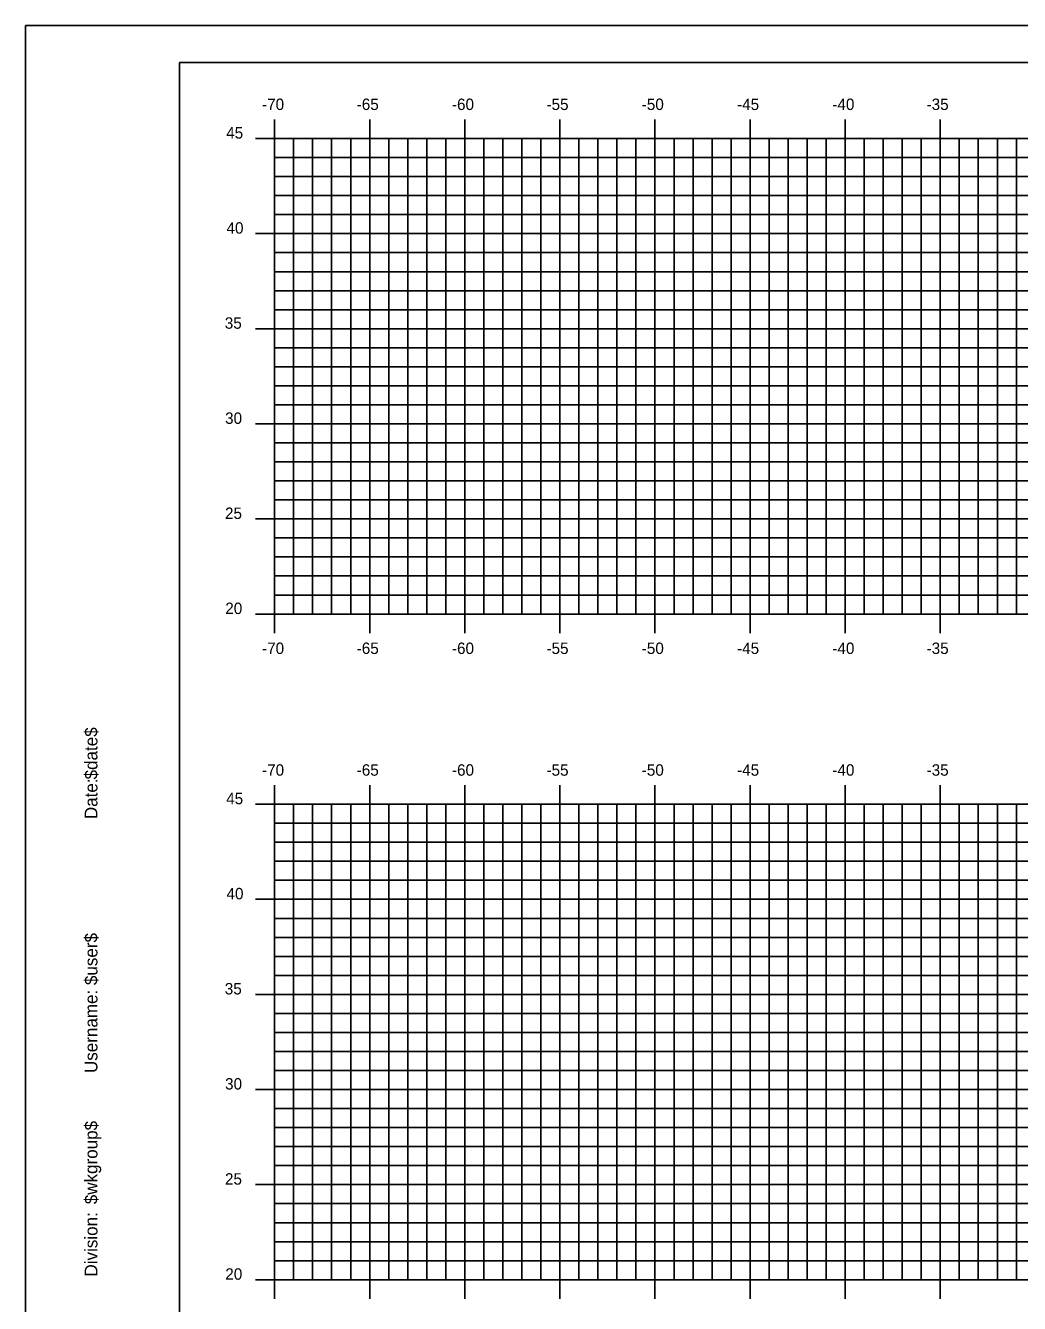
# Model space of a CAD drawing. Extents: x 1025909 to 1026079, y 394697 to 394807.
# Drawn here: x 1025908.6 to 1025960.8, y 394739.4 to 394806.5 of the extents above; entities that cross this region are included whole.
import ezdxf

# ---------------------------------------------------------------- set-up
doc = ezdxf.new("R2010")
doc.units = 0
for name, color, linetype in [('BORDER', 7, 'Continuous'), ('H_V ANNOTATION', 7, 'Continuous'), ('MAJOR', 7, 'Continuous'), ('MINOR', 7, 'Continuous'), ('PLOT BOUNDARY', 7, 'Continuous')]:
    doc.layers.add(name, color=color, linetype=linetype)

msp = doc.modelspace()

# ---------------------------------------------------------------- linework, layer by layer
at = {"layer": 'BORDER'}
for p, q in [((1026076.677, 394804.607), (1025916.677, 394804.607)), ((1025916.677, 394804.607), (1025916.677, 394699.607))]:
    msp.add_line(p, q, dxfattribs=at)
at = {"layer": 'MAJOR'}
for p, q in [((1025921.677, 394801.609), (1025921.677, 394800.607)), ((1025926.677, 394801.609), (1025926.677, 394800.607)), ((1025931.677, 394801.609), (1025931.677, 394800.607)), ((1025936.677, 394801.609), (1025936.677, 394800.607)), ((1025941.677, 394801.609), (1025941.677, 394800.607)), ((1025946.677, 394801.609), (1025946.677, 394800.607)), ((1025951.677, 394801.609), (1025951.677, 394800.607)), ((1025956.677, 394801.609), (1025956.677, 394800.607)), ((1025920.675, 394800.607), (1025921.677, 394800.607)), ((1025921.677, 394800.607), (1026061.677, 394800.607)), ((1025921.677, 394775.607), (1025921.677, 394800.607)), ((1025926.677, 394775.607), (1025926.677, 394800.607)), ((1025931.677, 394775.607), (1025931.677, 394800.607)), ((1025936.677, 394775.607), (1025936.677, 394800.607)), ((1025941.677, 394775.607), (1025941.677, 394800.607)), ((1025946.677, 394775.607), (1025946.677, 394800.607)), ((1025951.677, 394775.607), (1025951.677, 394800.607)), ((1025956.677, 394775.607), (1025956.677, 394800.607)), ((1025920.675, 394795.607), (1025921.677, 394795.607)), ((1025921.677, 394795.607), (1026061.677, 394795.607)), ((1025920.675, 394790.607), (1025921.677, 394790.607)), ((1025921.677, 394790.607), (1026061.677, 394790.607)), ((1025920.675, 394785.607), (1025921.677, 394785.607)), ((1025921.677, 394785.607), (1026061.677, 394785.607)), ((1025920.675, 394780.607), (1025921.677, 394780.607)), ((1025921.677, 394780.607), (1026061.677, 394780.607)), ((1025920.675, 394775.607), (1025921.677, 394775.607)), ((1025921.677, 394775.607), (1026061.677, 394775.607)), ((1025921.677, 394774.605), (1025921.677, 394775.607)), ((1025926.677, 394774.605), (1025926.677, 394775.607)), ((1025931.677, 394774.605), (1025931.677, 394775.607)), ((1025936.677, 394774.605), (1025936.677, 394775.607)), ((1025941.677, 394774.605), (1025941.677, 394775.607)), ((1025946.677, 394774.605), (1025946.677, 394775.607)), ((1025951.677, 394774.605), (1025951.677, 394775.607)), ((1025956.677, 394774.605), (1025956.677, 394775.607)), ((1025921.677, 394766.609), (1025921.677, 394765.607)), ((1025926.677, 394766.609), (1025926.677, 394765.607)), ((1025931.677, 394766.609), (1025931.677, 394765.607)), ((1025936.677, 394766.609), (1025936.677, 394765.607)), ((1025941.677, 394766.609), (1025941.677, 394765.607)), ((1025946.677, 394766.609), (1025946.677, 394765.607)), ((1025951.677, 394766.609), (1025951.677, 394765.607)), ((1025956.677, 394766.609), (1025956.677, 394765.607)), ((1025920.675, 394765.607), (1025921.677, 394765.607)), ((1025921.677, 394765.607), (1026061.677, 394765.607)), ((1025921.677, 394740.607), (1025921.677, 394765.607)), ((1025926.677, 394740.607), (1025926.677, 394765.607)), ((1025931.677, 394740.607), (1025931.677, 394765.607)), ((1025936.677, 394740.607), (1025936.677, 394765.607)), ((1025941.677, 394740.607), (1025941.677, 394765.607)), ((1025946.677, 394740.607), (1025946.677, 394765.607)), ((1025951.677, 394740.607), (1025951.677, 394765.607)), ((1025956.677, 394740.607), (1025956.677, 394765.607)), ((1025920.675, 394760.607), (1025921.677, 394760.607)), ((1025921.677, 394760.607), (1026061.677, 394760.607)), ((1025920.675, 394755.607), (1025921.677, 394755.607)), ((1025921.677, 394755.607), (1026061.677, 394755.607)), ((1025920.675, 394750.607), (1025921.677, 394750.607)), ((1025921.677, 394750.607), (1026061.677, 394750.607)), ((1025920.675, 394745.607), (1025921.677, 394745.607)), ((1025921.677, 394745.607), (1026061.677, 394745.607)), ((1025920.675, 394740.607), (1025921.677, 394740.607)), ((1025921.677, 394740.607), (1026061.677, 394740.607)), ((1025921.677, 394739.605), (1025921.677, 394740.607)), ((1025926.677, 394739.605), (1025926.677, 394740.607)), ((1025931.677, 394739.605), (1025931.677, 394740.607)), ((1025936.677, 394739.605), (1025936.677, 394740.607)), ((1025941.677, 394739.605), (1025941.677, 394740.607)), ((1025946.677, 394739.605), (1025946.677, 394740.607)), ((1025951.677, 394739.605), (1025951.677, 394740.607)), ((1025956.677, 394739.605), (1025956.677, 394740.607))]:
    msp.add_line(p, q, dxfattribs=at)
at = {"layer": 'MINOR'}
for p, q in [((1025922.677, 394775.607), (1025922.677, 394800.607)), ((1025923.677, 394775.607), (1025923.677, 394800.607)), ((1025924.677, 394775.607), (1025924.677, 394800.607)), ((1025925.677, 394775.607), (1025925.677, 394800.607)), ((1025927.677, 394775.607), (1025927.677, 394800.607)), ((1025928.677, 394775.607), (1025928.677, 394800.607)), ((1025929.677, 394775.607), (1025929.677, 394800.607)), ((1025930.677, 394775.607), (1025930.677, 394800.607)), ((1025932.677, 394775.607), (1025932.677, 394800.607)), ((1025933.677, 394775.607), (1025933.677, 394800.607)), ((1025934.677, 394775.607), (1025934.677, 394800.607)), ((1025935.677, 394775.607), (1025935.677, 394800.607)), ((1025937.677, 394775.607), (1025937.677, 394800.607)), ((1025938.677, 394775.607), (1025938.677, 394800.607)), ((1025939.677, 394775.607), (1025939.677, 394800.607)), ((1025940.677, 394775.607), (1025940.677, 394800.607)), ((1025942.677, 394775.607), (1025942.677, 394800.607)), ((1025943.677, 394775.607), (1025943.677, 394800.607)), ((1025944.677, 394775.607), (1025944.677, 394800.607)), ((1025945.677, 394775.607), (1025945.677, 394800.607)), ((1025947.677, 394775.607), (1025947.677, 394800.607)), ((1025948.677, 394775.607), (1025948.677, 394800.607)), ((1025949.677, 394775.607), (1025949.677, 394800.607)), ((1025950.677, 394775.607), (1025950.677, 394800.607)), ((1025952.677, 394775.607), (1025952.677, 394800.607)), ((1025953.677, 394775.607), (1025953.677, 394800.607)), ((1025954.677, 394775.607), (1025954.677, 394800.607)), ((1025955.677, 394775.607), (1025955.677, 394800.607)), ((1025957.677, 394775.607), (1025957.677, 394800.607)), ((1025958.677, 394775.607), (1025958.677, 394800.607)), ((1025959.677, 394775.607), (1025959.677, 394800.607)), ((1025960.677, 394775.607), (1025960.677, 394800.607)), ((1025921.677, 394799.607), (1026061.677, 394799.607)), ((1025921.677, 394799.607), (1025922.679, 394799.607)), ((1025921.677, 394798.607), (1026061.677, 394798.607)), ((1025921.677, 394798.607), (1025922.679, 394798.607)), ((1025921.677, 394797.607), (1026061.677, 394797.607)), ((1025921.677, 394797.607), (1025922.679, 394797.607)), ((1025921.677, 394796.607), (1026061.677, 394796.607)), ((1025921.677, 394796.607), (1025922.679, 394796.607)), ((1025921.677, 394794.607), (1026061.677, 394794.607)), ((1025921.677, 394794.607), (1025922.679, 394794.607)), ((1025921.677, 394793.607), (1026061.677, 394793.607)), ((1025921.677, 394793.607), (1025922.679, 394793.607)), ((1025921.677, 394792.607), (1026061.677, 394792.607)), ((1025921.677, 394792.607), (1025922.679, 394792.607)), ((1025921.677, 394791.607), (1026061.677, 394791.607)), ((1025921.677, 394791.607), (1025922.679, 394791.607)), ((1025921.677, 394789.607), (1026061.677, 394789.607)), ((1025921.677, 394789.607), (1025922.679, 394789.607)), ((1025921.677, 394788.607), (1026061.677, 394788.607)), ((1025921.677, 394788.607), (1025922.679, 394788.607)), ((1025921.677, 394787.607), (1026061.677, 394787.607)), ((1025921.677, 394787.607), (1025922.679, 394787.607)), ((1025921.677, 394786.607), (1026061.677, 394786.607)), ((1025921.677, 394786.607), (1025922.679, 394786.607)), ((1025921.677, 394784.607), (1026061.677, 394784.607)), ((1025921.677, 394784.607), (1025922.679, 394784.607)), ((1025921.677, 394783.607), (1026061.677, 394783.607)), ((1025921.677, 394783.607), (1025922.679, 394783.607)), ((1025921.677, 394782.607), (1026061.677, 394782.607)), ((1025921.677, 394782.607), (1025922.679, 394782.607)), ((1025921.677, 394781.607), (1026061.677, 394781.607)), ((1025921.677, 394781.607), (1025922.679, 394781.607)), ((1025921.677, 394779.607), (1026061.677, 394779.607)), ((1025921.677, 394779.607), (1025922.679, 394779.607)), ((1025921.677, 394778.607), (1026061.677, 394778.607)), ((1025921.677, 394778.607), (1025922.679, 394778.607)), ((1025921.677, 394777.607), (1026061.677, 394777.607)), ((1025921.677, 394777.607), (1025922.679, 394777.607)), ((1025921.677, 394776.607), (1026061.677, 394776.607)), ((1025921.677, 394776.607), (1025922.679, 394776.607)), ((1025922.677, 394740.607), (1025922.677, 394765.607)), ((1025923.677, 394740.607), (1025923.677, 394765.607)), ((1025924.677, 394740.607), (1025924.677, 394765.607)), ((1025925.677, 394740.607), (1025925.677, 394765.607)), ((1025927.677, 394740.607), (1025927.677, 394765.607)), ((1025928.677, 394740.607), (1025928.677, 394765.607)), ((1025929.677, 394740.607), (1025929.677, 394765.607)), ((1025930.677, 394740.607), (1025930.677, 394765.607)), ((1025932.677, 394740.607), (1025932.677, 394765.607)), ((1025933.677, 394740.607), (1025933.677, 394765.607)), ((1025934.677, 394740.607), (1025934.677, 394765.607)), ((1025935.677, 394740.607), (1025935.677, 394765.607)), ((1025937.677, 394740.607), (1025937.677, 394765.607)), ((1025938.677, 394740.607), (1025938.677, 394765.607)), ((1025939.677, 394740.607), (1025939.677, 394765.607)), ((1025940.677, 394740.607), (1025940.677, 394765.607)), ((1025942.677, 394740.607), (1025942.677, 394765.607)), ((1025943.677, 394740.607), (1025943.677, 394765.607)), ((1025944.677, 394740.607), (1025944.677, 394765.607)), ((1025945.677, 394740.607), (1025945.677, 394765.607)), ((1025947.677, 394740.607), (1025947.677, 394765.607)), ((1025948.677, 394740.607), (1025948.677, 394765.607)), ((1025949.677, 394740.607), (1025949.677, 394765.607)), ((1025950.677, 394740.607), (1025950.677, 394765.607)), ((1025952.677, 394740.607), (1025952.677, 394765.607)), ((1025953.677, 394740.607), (1025953.677, 394765.607)), ((1025954.677, 394740.607), (1025954.677, 394765.607)), ((1025955.677, 394740.607), (1025955.677, 394765.607)), ((1025957.677, 394740.607), (1025957.677, 394765.607)), ((1025958.677, 394740.607), (1025958.677, 394765.607)), ((1025959.677, 394740.607), (1025959.677, 394765.607)), ((1025960.677, 394740.607), (1025960.677, 394765.607)), ((1025921.677, 394764.607), (1026061.677, 394764.607)), ((1025921.677, 394764.607), (1025922.679, 394764.607)), ((1025921.677, 394763.607), (1026061.677, 394763.607)), ((1025921.677, 394763.607), (1025922.679, 394763.607)), ((1025921.677, 394762.607), (1026061.677, 394762.607)), ((1025921.677, 394762.607), (1025922.679, 394762.607)), ((1025921.677, 394761.607), (1026061.677, 394761.607)), ((1025921.677, 394761.607), (1025922.679, 394761.607)), ((1025921.677, 394759.607), (1026061.677, 394759.607)), ((1025921.677, 394759.607), (1025922.679, 394759.607)), ((1025921.677, 394758.607), (1026061.677, 394758.607)), ((1025921.677, 394758.607), (1025922.679, 394758.607)), ((1025921.677, 394757.607), (1026061.677, 394757.607)), ((1025921.677, 394757.607), (1025922.679, 394757.607)), ((1025921.677, 394756.607), (1026061.677, 394756.607)), ((1025921.677, 394756.607), (1025922.679, 394756.607)), ((1025921.677, 394754.607), (1026061.677, 394754.607)), ((1025921.677, 394754.607), (1025922.679, 394754.607)), ((1025921.677, 394753.607), (1026061.677, 394753.607)), ((1025921.677, 394753.607), (1025922.679, 394753.607)), ((1025921.677, 394752.607), (1026061.677, 394752.607)), ((1025921.677, 394752.607), (1025922.679, 394752.607)), ((1025921.677, 394751.607), (1026061.677, 394751.607)), ((1025921.677, 394751.607), (1025922.679, 394751.607)), ((1025921.677, 394749.607), (1026061.677, 394749.607)), ((1025921.677, 394749.607), (1025922.679, 394749.607)), ((1025921.677, 394748.607), (1026061.677, 394748.607)), ((1025921.677, 394748.607), (1025922.679, 394748.607)), ((1025921.677, 394747.607), (1026061.677, 394747.607)), ((1025921.677, 394747.607), (1025922.679, 394747.607)), ((1025921.677, 394746.607), (1026061.677, 394746.607)), ((1025921.677, 394746.607), (1025922.679, 394746.607)), ((1025921.677, 394744.607), (1026061.677, 394744.607)), ((1025921.677, 394744.607), (1025922.679, 394744.607)), ((1025921.677, 394743.607), (1026061.677, 394743.607)), ((1025921.677, 394743.607), (1025922.679, 394743.607)), ((1025921.677, 394742.607), (1026061.677, 394742.607)), ((1025921.677, 394742.607), (1025922.679, 394742.607)), ((1025921.677, 394741.607), (1026061.677, 394741.607)), ((1025921.677, 394741.607), (1025922.679, 394741.607))]:
    msp.add_line(p, q, dxfattribs=at)
at = {"layer": 'PLOT BOUNDARY'}
msp.add_lwpolyline([(1025908.583, 394696.548), (1026078.583, 394696.548), (1026078.583, 394806.548), (1025908.583, 394806.548)], close=True, dxfattribs=at)

# ---------------------------------------------------------------- texts
at = {"layer": 'BORDER'}
for s, p in [('$date$', (1025912.362, 394766.912)), ('Date:', (1025912.362, 394764.824)), ('$user$', (1025912.362, 394756.098)), ('Username:', (1025912.362, 394751.474)), ('$wkgroup$', (1025912.362, 394744.576)), ('Division:', (1025912.362, 394740.773))]:
    msp.add_text(s, height=0.6696, rotation=90, dxfattribs=at).set_placement(p)
at = {"layer": 'H_V ANNOTATION'}
for s, p in [('-70', (1025921.018, 394802.107)), ('-65', (1025925.994, 394802.107)), ('-60', (1025931.002, 394802.107)), ('-55', (1025935.973, 394802.107)), ('-50', (1025940.981, 394802.107)), ('-45', (1025945.994, 394802.107)), ('-40', (1025951.002, 394802.107)), ('-35', (1025955.957, 394802.107)), ('45', (1025919.133, 394800.607)), ('40', (1025919.149, 394795.607)), ('35', (1025919.058, 394790.607)), ('30', (1025919.074, 394785.607)), ('25', (1025919.069, 394780.607)), ('20', (1025919.085, 394775.607)), ('-70', (1025921.018, 394773.507)), ('-65', (1025925.994, 394773.507)), ('-60', (1025931.002, 394773.507)), ('-55', (1025935.973, 394773.507)), ('-50', (1025940.981, 394773.507)), ('-45', (1025945.994, 394773.507)), ('-40', (1025951.002, 394773.507)), ('-35', (1025955.957, 394773.507)), ('-70', (1025921.018, 394767.107)), ('-65', (1025925.994, 394767.107)), ('-60', (1025931.002, 394767.107)), ('-55', (1025935.973, 394767.107)), ('-50', (1025940.981, 394767.107)), ('-45', (1025945.994, 394767.107)), ('-40', (1025951.002, 394767.107)), ('-35', (1025955.957, 394767.107)), ('45', (1025919.133, 394765.607)), ('40', (1025919.149, 394760.607)), ('35', (1025919.058, 394755.607)), ('30', (1025919.074, 394750.607)), ('25', (1025919.069, 394745.607)), ('20', (1025919.085, 394740.607))]:
    msp.add_text(s, height=0.6, dxfattribs=at).set_placement(p)

doc.saveas('drawing.dxf')
